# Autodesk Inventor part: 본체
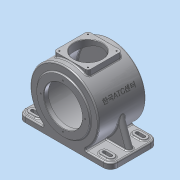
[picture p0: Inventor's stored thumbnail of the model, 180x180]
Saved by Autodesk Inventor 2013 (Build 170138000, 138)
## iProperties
Created: 2015-06
Part Number: 본체
Material: 알루미늄 6061
Document SubType Name: Modeling
Designer: Administrator
Mass: 3275.78 g
Surface Area: 2302.33 cm^2
Volume: 1208.77 cm^3
Density: 2.71 g/cm^3
Author: Administrator
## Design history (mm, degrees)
sketch "스케치1" dims "d0" = 170
  geometry: L1 (0, 0)-(0, -85); L2 (85, 0)-(0, 0); L3 (0, 0)-(77.036, 35.923); C1 r 77 at (0, 0); C2 r 65 at (0, 0); C3 r 31 at (0, 0); 2 further points
  constraints: 6 end point, 4 coincident, 3 centre point, 1 horizontal alignment, 1 perpendicular, 1 vertical, 2 other
  dimensions: "d1" = 154 diameter of C1; "d2" = 130 diameter of C2; "d29" = 62 diameter of C3; "d90" = 85 distance of L2.end L3.end; "d91" = 25 deg angle of L3 L2
extrude "돌출1" new body sketch "스케치1" stored distance "d3" = 118; taper "d4" = 0 deg
node "작업 평면1"
sketch "스케치2"
  geometry: L1 (-97, 59)-(97, 59); L2 (115, 41)-(115, -41); L3 (97, -59)-(-97, -59); L4 (-115, -41)-(-115, 41); L5 (-115, 59)-(115, -59); L6 (115, 59)-(-115, -59); L7 (97, -32)-(81, -32); L8 (97, -50)-(81, -50); L9 (97, -45)-(81, -45); L10 (97, -37)-(81, -37); L11 (115, 0)-(-115, 0); L12 (0, -59)-(0, 59); L13 (-115, 0)-(115, 0); L14 (-97, -50)-(-81, -50); L15 (-97, -32)-(-81, -32); L16 (-97, -37)-(-81, -37); L17 (-97, -45)-(-81, -45); L18 (97, 32)-(81, 32); L19 (97, 37)-(81, 37); L20 (97, 50)-(81, 50); L21 (97, 45)-(81, 45); L22 (-97, 50)-(-81, 50); L23 (-97, 45)-(-81, 45); L24 (-97, 37)-(-81, 37); L25 (-97, 32)-(-81, 32); A1 r 18 centre (97, -41) between (97, -59) and (115, -41); A2 r 18 centre (97, 41) between (115, 41) and (97, 59); A3 r 18 centre (-97, 41) between (-97, 59) and (-115, 41); A4 r 18 centre (-97, -41) between (-115, -41) and (-97, -59); A5 r 9 centre (97, -41) between (97, -50) and (97, -32); A6 r 9 centre (81, -41) between (81, -32) and (81, -50); A7 r 4 centre (97, -41) between (97, -45) and (97, -37); A8 r 4 centre (81, -41) between (81, -37) and (81, -45); A9 r 9 centre (-97, -41) between (-97, -32) and (-97, -50); A10 r 9 centre (-81, -41) between (-81, -50) and (-81, -32); A11 r 4 centre (-97, -41) between (-97, -37) and (-97, -45); A12 r 4 centre (-81, -41) between (-81, -45) and (-81, -37); A13 r 9 centre (81, 41) between (81, 50) and (81, 32); A14 r 4 centre (97, 41) between (97, 37) and (97, 45); A15 r 9 centre (97, 41) between (97, 32) and (97, 50); A16 r 4 centre (81, 41) between (81, 45) and (81, 37); A17 r 9 centre (-81, 41) between (-81, 32) and (-81, 50); A18 r 4 centre (-81, 41) between (-81, 37) and (-81, 45); A19 r 4 centre (-97, 41) between (-97, 45) and (-97, 37); A20 r 9 centre (-97, 41) between (-97, 50) and (-97, 32); 3 further points
  constraints: 50 end point, 40 point on circle, 40 symmetric about line, 20 centre point, 16 tangent, 8 coincident, 8 point on line, 6 midpoint, 3 equal radius, 2 parallel, 1 horizontal, 1 horizontal alignment, 1 perpendicular, 12 other
  dimensions: "d7" = 230 distance of L5.end L6.end; "d8" = 118 distance of L6.start L5.end; "d9" = 18 radius of A1; "d12" = 18 diameter of A5; "d13" = 18 diameter of A6; "d14" = 8 diameter of A7; "d15" = 8 diameter of A8; "d16" = 97 horizontal distance of A7.centre point (0, 0); "d17" = 16 distance of A8.centre A5.centre; "d18" = 41 vertical distance of A5.centre point (0, 0)
extrude "돌출2" join sketch "스케치2" distance "d10" = 14; taper "d11" = 0 deg
sketch "스케치3"
  geometry: L1 (-97, 50)-(-81, 50) reference; L2 (115, -59)-(-115, 59) reference; L3 (-97, 45)-(-81, 45) reference; L4 (-97, 37)-(-81, 37) reference; L5 (-97, 32)-(-81, 32) reference; L6 (-97, -59)-(97, -59) reference; L7 (-115, 41)-(-115, -41) reference; L8 (97, 59)-(-97, 59) reference; L9 (115, -41)-(115, 41) reference; L10 (-97, -37)-(-81, -37) reference; L11 (-97, -45)-(-81, -45) reference; L12 (-115, -59)-(115, 59) reference; L13 (-97, -32)-(-81, -32) reference; L14 (-97, -50)-(-81, -50) reference; L15 (97, 37)-(81, 37) reference; L16 (97, 45)-(81, 45) reference; L17 (97, 50)-(81, 50) reference; L18 (97, 32)-(81, 32) reference; L19 (97, -37)-(81, -37) reference; L20 (97, -45)-(81, -45) reference; L21 (97, -32)-(81, -32) reference; L22 (97, -50)-(81, -50) reference; A1 r 9 centre (-97, 41) between (-97, 50) and (-97, 32) reference; A2 r 9 centre (-81, 41) between (-81, 32) and (-81, 50) reference; A3 r 4 centre (-81, 41) between (-81, 37) and (-81, 45) reference; A4 r 4 centre (-97, 41) between (-97, 45) and (-97, 37) reference; A5 r 18 centre (-97, -41) between (-115, -41) and (-97, -59) reference; A6 r 18 centre (-97, 41) between (-97, 59) and (-115, 41) reference; A7 r 18 centre (97, 41) between (115, 41) and (97, 59) reference; A8 r 18 centre (97, -41) between (97, -59) and (115, -41) reference; A9 r 4 centre (-97, -41) between (-97, -37) and (-97, -45) reference; A10 r 4 centre (-81, -41) between (-81, -45) and (-81, -37) reference; A11 r 9 centre (-97, -41) between (-97, -32) and (-97, -50) reference; A12 r 9 centre (-81, -41) between (-81, -50) and (-81, -32) reference; A13 r 4 centre (81, 41) between (81, 45) and (81, 37) reference; A14 r 9 centre (81, 41) between (81, 50) and (81, 32) reference; A15 r 4 centre (97, 41) between (97, 37) and (97, 45) reference; A16 r 9 centre (97, 41) between (97, 32) and (97, 50) reference; A17 r 4 centre (81, -41) between (81, -37) and (81, -45) reference; A18 r 9 centre (81, -41) between (81, -32) and (81, -50) reference; A19 r 4 centre (97, -41) between (97, -45) and (97, -37) reference; A20 r 9 centre (97, -41) between (97, -50) and (97, -32) reference; 1 further point
  node "투영된 루프1"
extrude "돌출3" join sketch "스케치3" distance "d19" = 3; taper "d20" = 0 deg
extrude "돌출4" cut sketch "스케치3" stored distance "d21" = 3; taper "d22" = 0 deg
extrude "돌출5" join sketch "스케치1" distance "d23" = 62; taper "d25" = 0 deg; dims "d24" = 72, "d26" = 0
extrude "돌출6" cut sketch "스케치1" stored distance "d27" = 102; taper "d28" = 0 deg
hole "구멍1" diameter "d32" = 95; stored, may be unused: countersink angle "d36" = 90 deg, drill point angle "d38" = 0 deg; dims "d30" = 10, "d31" = 10, "d33" = 6, "d34" = 4, "d35" = 2, "d37" = 11
sketch "스케치4"
  geometry: C1 r 31 at (0, 0) reference
extrude "돌출7" join sketch "스케치4" distance "d39" = 3.5; taper "d40" = -25 deg
hole "구멍2" diameter "d43" = 30; stored, may be unused: countersink angle "d47" = 90 deg, drill point angle "d49" = 0 deg; dims "d41" = 10, "d42" = 10, "d44" = 6, "d45" = 47, "d46" = 14, "d48" = 17
node "작업 평면2"
sketch "스케치5"
  geometry: L1 (42.5, -42.5)-(-42.5, -42.5); L2 (-42.5, -42.5)-(-42.5, 42.5); L3 (-42.5, 42.5)-(42.5, 42.5); L4 (42.5, 42.5)-(42.5, -42.5); L5 (42.5, -42.5)-(-42.5, 42.5); L6 (-42.5, -42.5)-(42.5, 42.5); 1 further point
  constraints: 12 end point, 2 midpoint, 2 parallel, 1 horizontal, 1 perpendicular
  dimensions: "d51" = 85 distance of L2.end L3.end; "d52" = 85 distance of L1.end L2.end
extrude "돌출8" join sketch "스케치5" stored distance "d53" = 3.5; taper "d54" = 0 deg
sketch "스케치6"
  geometry: 1 further point
hole "구멍3" sketch "스케치6" at (0, 0) diameter "d55" = 70; stored, may be unused: countersink angle "d59" = 90 deg, drill point angle "d61" = 0 deg; dims "d56" = 6, "d57" = 47, "d58" = 14, "d60" = 17
sketch "스케치7"
  geometry: L1 (-42.5, 42.5)-(42.5, 42.5) reference; L2 (-42.5, -42.5)-(-42.5, 42.5) reference; C1 r 35 at (0, 0) reference; 4 further points
  constraints: 1 horizontal, 1 vertical, 3 other
  dimensions: "d62" = 35.5 horizontal distance of point (-35.5, 35.5) C1.centre; "d63" = 35.5 horizontal distance of point (-35.5, 35.5) C1.centre; "d66" = 71 distance of point (-35.5, 35.5) point (35.5, 35.5); "d69" = 71 distance of point (-35.5, 35.5) point (-35.5, -35.5)
hole "구멍4" sketch "스케치7" at (-35.5, 35.5), (35.5, 35.5), (-35.5, -35.5), (35.5, -35.5) diameter "d72" = 3.242; stored, may be unused: countersink angle "d76" = 90 deg, drill point angle "d78" = 118 deg; dims "d73" = 10, "d74" = 47, "d75" = 14, "d77" = 13
sketch "스케치8"
  geometry: C1 r 47.5 at (0, 0) reference; 1 further point
  constraints: 1 vertical alignment
  dimensions: "d79" = 55 distance of point (0, 55) C1.centre
hole "구멍5" sketch "스케치8" at (0, 55) diameter "d80" = 3.242; stored, may be unused: countersink angle "d84" = 90 deg, drill point angle "d86" = 0 deg; dims "d81" = 8, "d82" = 47, "d83" = 14, "d85" = 8
node "작업 평면3"
sketch "스케치9"
  geometry: 2 further points
  constraints: 1 other
feature "엠보싱1" sketch "스케치9" dims "d0" = 170, "d1" = 154, "d2" = 130, "d10" = 14, "d29" = 62, "d90" = 85, "d91" = 25 deg, "d92" = 0.5, "d93" = 0
chamfer "모따기1" distance "d94" = 1; stored, may be unused: second distance "d95" = 2, angle "d96" = 45 deg
fillet "모깎기1" dims "d97" = 0.3
fillet "모깎기7" dims "d121" = 7
fillet "모깎기8" dims "d122" = 3
sketch "스케치11"
  geometry: L1 (-97, -71)-(-115, -71) reference; L2 (-109, -71)-(-84.87, -4.703); L3 (-115, -85)-(-115, -71) reference; L4 (-109, -71)-(-46.733, -71); A1 r 85 centre (0, 0) between (46.733, -71) and (-46.733, -71) reference; 1 further point
  constraints: 4 end point, 1 perpendicular, 1 point on circle, 1 point on line
  dimensions: "d114" = 6 distance from line of L2.start L3; "d115" = 110 deg angle of L2 L1; "d116" = 85 radius of A1 (derived)
extrude "돌출10" join sketch "스케치11" stored distance "d117" = 15; taper "d118" = 0 deg
fillet "모깎기5" dims "d119" = 7.5
fillet "모깎기6" dims "d120" = 3
fillet "모깎기9" dims "d123" = 3
node "솔리드1"
pattern_circular "원형 패턴1" dims angle "d88" = 360 deg
mirror "대칭2"
other parameters: "d5" = -85, "d50" = 88
